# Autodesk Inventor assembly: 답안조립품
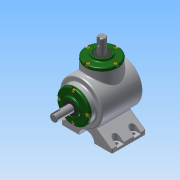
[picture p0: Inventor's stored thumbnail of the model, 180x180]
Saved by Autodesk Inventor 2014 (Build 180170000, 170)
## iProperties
Created: 2017-04
Part Number: 답안조립품
Document SubType Name: Assembly
Designer: NET
Author: NET
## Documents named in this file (14)
- C:\Users\NET\Desktop\470407V1016\답안조립품.iam
- C:\Users\NET\Desktop\470407V1016\본체.ipt
- C:\Users\NET\Desktop\470407V1016\메인 베벨기어.ipt
- C:\Users\NET\Desktop\470407V1016\메인 축.ipt
- 메인 축.ipt
- C:\Users\NET\Desktop\470407V1016\베어링 6203.ipt
- C:\Users\NET\Desktop\470407V1016\볼트 M4.ipt
- C:\Users\NET\Desktop\470407V1016\서브 베벨기어.ipt
- C:\Users\NET\Desktop\470407V1016\서브 축.ipt
- 서브 축.ipt
- C:\Users\NET\Desktop\470407V1016\오일실 17 32 8.ipt
- C:\Users\NET\Desktop\470407V1016\커버.ipt
- C:\Users\NET\Desktop\470407V1016\키 4x4.ipt
- C:\Users\NET\Desktop\470407V1016\키 5x5.ipt
## Named parameters: d14_d13 = 0
